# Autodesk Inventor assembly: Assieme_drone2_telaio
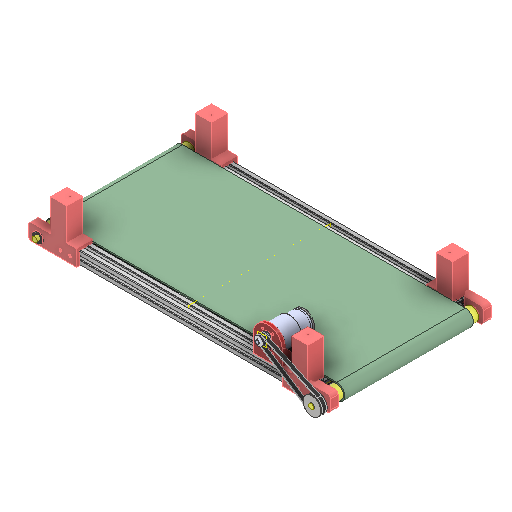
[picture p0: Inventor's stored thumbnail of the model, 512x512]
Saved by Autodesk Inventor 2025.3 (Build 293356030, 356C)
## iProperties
Created: 2025-05
Part Number: Assieme_drone2_telaio
Document SubType Name: Assembly
Designer: R5800u
Author: R5800u
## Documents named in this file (20)
- C:\Users\R5800u\Desktop\nastro_trasportatore_01\Assieme_drone2_telaio.iam
- C:\Users\R5800u\Desktop\nastro_trasportatore_01\tslot-20x20-1.ipt
- C:\Users\R5800u\Desktop\nastro_trasportatore_01\tslot-20x20-1_MIR.ipt
- C:\Users\R5800u\Desktop\nastro_trasportatore_01\tslot-20x20-2.ipt
- C:\Users\R5800u\Desktop\nastro_trasportatore_01\SNSD20x20.ipt
- C:\Users\R5800u\Desktop\nastro_trasportatore_01\SNSD20x20_MIR.ipt
- C:\Users\R5800u\Desktop\nastro_trasportatore_01\MM-JGB37 v4_MIR_MIR.ipt
- C:\Users\R5800u\Desktop\nastro_trasportatore_01\JGB37-520_MIR_MIR.ipt
- C:\Users\R5800u\Desktop\nastro_trasportatore_01\lato.ipt
- C:\Users\R5800u\Desktop\nastro_trasportatore_01\cilindro_01.ipt
- C:\Users\R5800u\Desktop\nastro_trasportatore_01\piastra_laterale_cilindro.ipt
- C:\Users\R5800u\Desktop\nastro_trasportatore_01\GT2 Timing Pulley T40 small.ipt
- C:\Users\R5800u\Desktop\nastro_trasportatore_01\GT2 16 Teeth Free Pulley.ipt
- C:\Users\R5800u\Documents\Inventor\Content Center Files\R2025\it-IT\BS 290 SKF(30)\BS 290 SKF - SKF 618_8.ipt
- C:\Users\R5800u\Desktop\nastro_trasportatore_01\piastra_laterale_cilindro_MIR.ipt
- C:\Users\R5800u\Desktop\nastro_trasportatore_01\piastra_laterale_cilindro_MIR1.ipt
- C:\Users\R5800u\Desktop\nastro_trasportatore_01\piastra_laterale_cilindro_MIR_MIR.ipt
- C:\Users\R5800u\Desktop\nastro_trasportatore_01\cilindro_02.ipt
- C:\Users\R5800u\Desktop\nastro_trasportatore_01\cinghia.ipt
- C:\Users\R5800u\Desktop\nastro_trasportatore_01\nastro.ipt
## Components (30 placed, 19 different names)
1. tslot-20x20-1:1
2. tslot-20x20-1_MIR:1
3. tslot-20x20-2:1
4. tslot-20x20-2:2
5. SNSD20x20:1 — Allineato:14, Coincidente:22, Coincidente:23
6. SNSD20x20:2 — Allineato:13, Coincidente:20, Coincidente:21
7. SNSD20x20_MIR:1 — Allineato:15, Coincidente:24, Coincidente:27
8. SNSD20x20_MIR:2 — Allineato:16, Coincidente:25, Coincidente:26
9. tslot-20x20-2:3 — Allineato:17, Coincidente:28, Allineato:30, Allineato:32, Coincidente:30, Allineato:33, Coincidente:31
10. SNSD20x20_MIR:3 — Allineato:32, Coincidente:29, Coincidente:30
11. SNSD20x20:3 — Allineato:33, Coincidente:31, Coincidente:32
12. MM-JGB37 v4_MIR_MIR:1 — Coincidente:54, Coincidente:55, Rotazionale:5, Coincidente:68, Allineato:55, Allineato:56
13. JGB37-520_MIR_MIR:1 — Coincidente:54, Coincidente:55, Rotazionale:5, Rotazionale:6
14. lato:1
15. cilindro_01:1 — Coincidente:69, Coincidente:70, Coincidente:71, Coincidente:73, Coincidente:76, Allineato:67
16. piastra_laterale_cilindro:1 — Coincidente:72, Allineato:64
17. GT2 16 Teeth Free Pulley:1 — Rotazionale:6, Coincidente:74
18. GT2 Timing Pulley T40 small:1 — Coincidente:73, Coincidente:74, Allineato:66
19. BS 290 SKF 618/8:1 — Allineato:64, Coincidente:77
20. BS 290 SKF 618/8:2 — Coincidente:76, Coincidente:77
21. piastra_laterale_cilindro_MIR:1 — Rotazionale:7
22. BS 290 SKF 618/8:3 — Rotazionale:8
23. BS 290 SKF 618/8:4 — Rotazionale:7, Rotazionale:8
24. cilindro_02:1
25. piastra_laterale_cilindro_MIR1:1 — Allineato:65
26. BS 290 SKF 618/8:5 — Allineato:65
27. piastra_laterale_cilindro_MIR_MIR:1 — Rotazionale:9
28. BS 290 SKF 618/8:6 — Rotazionale:9
29. cinghia:1 — Allineato:66
30. nastro:1 — Allineato:67
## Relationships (43: Mate 24, Flush 14, RevoluteJoint 5)
- Allineato:13 [Flush]: SNSD20x20:2
- Coincidente:20 [Mate]: SNSD20x20:2
- Coincidente:21 [Mate]: SNSD20x20:2
- Allineato:14 [Flush]: SNSD20x20:1
- Coincidente:22 [Mate]: SNSD20x20:1
- Coincidente:23 [Mate]: SNSD20x20:1
- Allineato:15 [Flush]: SNSD20x20_MIR:1
- Allineato:16 [Flush]: SNSD20x20_MIR:2
- Coincidente:24 [Mate]: SNSD20x20_MIR:1
- Coincidente:25 [Mate]: SNSD20x20_MIR:2
- Coincidente:26 [Mate]: SNSD20x20_MIR:2
- Coincidente:27 [Mate]: SNSD20x20_MIR:1
- Allineato:17 [Flush]: tslot-20x20-2:3
- Coincidente:28 [Mate]: tslot-20x20-2:3
- Allineato:30 [Flush]: tslot-20x20-2:3
- Allineato:32 [Flush]: tslot-20x20-2:3 ↔ SNSD20x20_MIR:3
- Coincidente:29 [Mate]: SNSD20x20_MIR:3
- Coincidente:30 [Mate]: tslot-20x20-2:3 ↔ SNSD20x20_MIR:3
- Allineato:33 [Flush]: tslot-20x20-2:3 ↔ SNSD20x20:3
- Coincidente:31 [Mate]: tslot-20x20-2:3 ↔ SNSD20x20:3
- Coincidente:32 [Mate]: SNSD20x20:3
- Coincidente:54 [Mate]: MM-JGB37 v4_MIR_MIR:1 ↔ JGB37-520_MIR_MIR:1
- Coincidente:55 [Mate]: MM-JGB37 v4_MIR_MIR:1 ↔ JGB37-520_MIR_MIR:1
- Rotazionale:5 [RevoluteJoint]: MM-JGB37 v4_MIR_MIR:1 ↔ JGB37-520_MIR_MIR:1
- Coincidente:68 [Mate]: MM-JGB37 v4_MIR_MIR:1
- Allineato:55 [Flush]: MM-JGB37 v4_MIR_MIR:1
- Allineato:56 [Flush]: MM-JGB37 v4_MIR_MIR:1
- Coincidente:69 [Mate]: cilindro_01:1
- Coincidente:70 [Mate]: cilindro_01:1
- Coincidente:71 [Mate]: cilindro_01:1
- Coincidente:72 [Mate]: piastra_laterale_cilindro:1
- Rotazionale:6 [RevoluteJoint]: JGB37-520_MIR_MIR:1 ↔ GT2 16 Teeth Free Pulley:1
- Coincidente:73 [Mate]: cilindro_01:1 ↔ GT2 Timing Pulley T40 small:1
- Coincidente:74 [Mate]: GT2 16 Teeth Free Pulley:1 ↔ GT2 Timing Pulley T40 small:1
- Allineato:64 [Flush]: piastra_laterale_cilindro:1 ↔ BS 290 SKF 618/8:1
- Coincidente:76 [Mate]: cilindro_01:1 ↔ BS 290 SKF 618/8:2
- Coincidente:77 [Mate]: BS 290 SKF 618/8:1 ↔ BS 290 SKF 618/8:2
- Rotazionale:7 [RevoluteJoint]: piastra_laterale_cilindro_MIR:1 ↔ BS 290 SKF 618/8:4
- Rotazionale:8 [RevoluteJoint]: BS 290 SKF 618/8:3 ↔ BS 290 SKF 618/8:4
- Allineato:65 [Flush]: piastra_laterale_cilindro_MIR1:1 ↔ BS 290 SKF 618/8:5
- Rotazionale:9 [RevoluteJoint]: piastra_laterale_cilindro_MIR_MIR:1 ↔ BS 290 SKF 618/8:6
- Allineato:66 [Flush]: GT2 Timing Pulley T40 small:1 ↔ cinghia:1
- Allineato:67 [Flush]: cilindro_01:1 ↔ nastro:1
## Named parameters: d358_d357 = 0
